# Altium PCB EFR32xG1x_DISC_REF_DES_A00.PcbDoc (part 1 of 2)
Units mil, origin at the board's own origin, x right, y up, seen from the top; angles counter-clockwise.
Board outline 1181.1 x 1771.65 mil, 4 copper layers (Top Layer, Signal Layer 2, Signal Layer 3, Bottom Layer), stack 63.229 mil thick; 88 components, 86 nets, 332 pads, 389 vias.
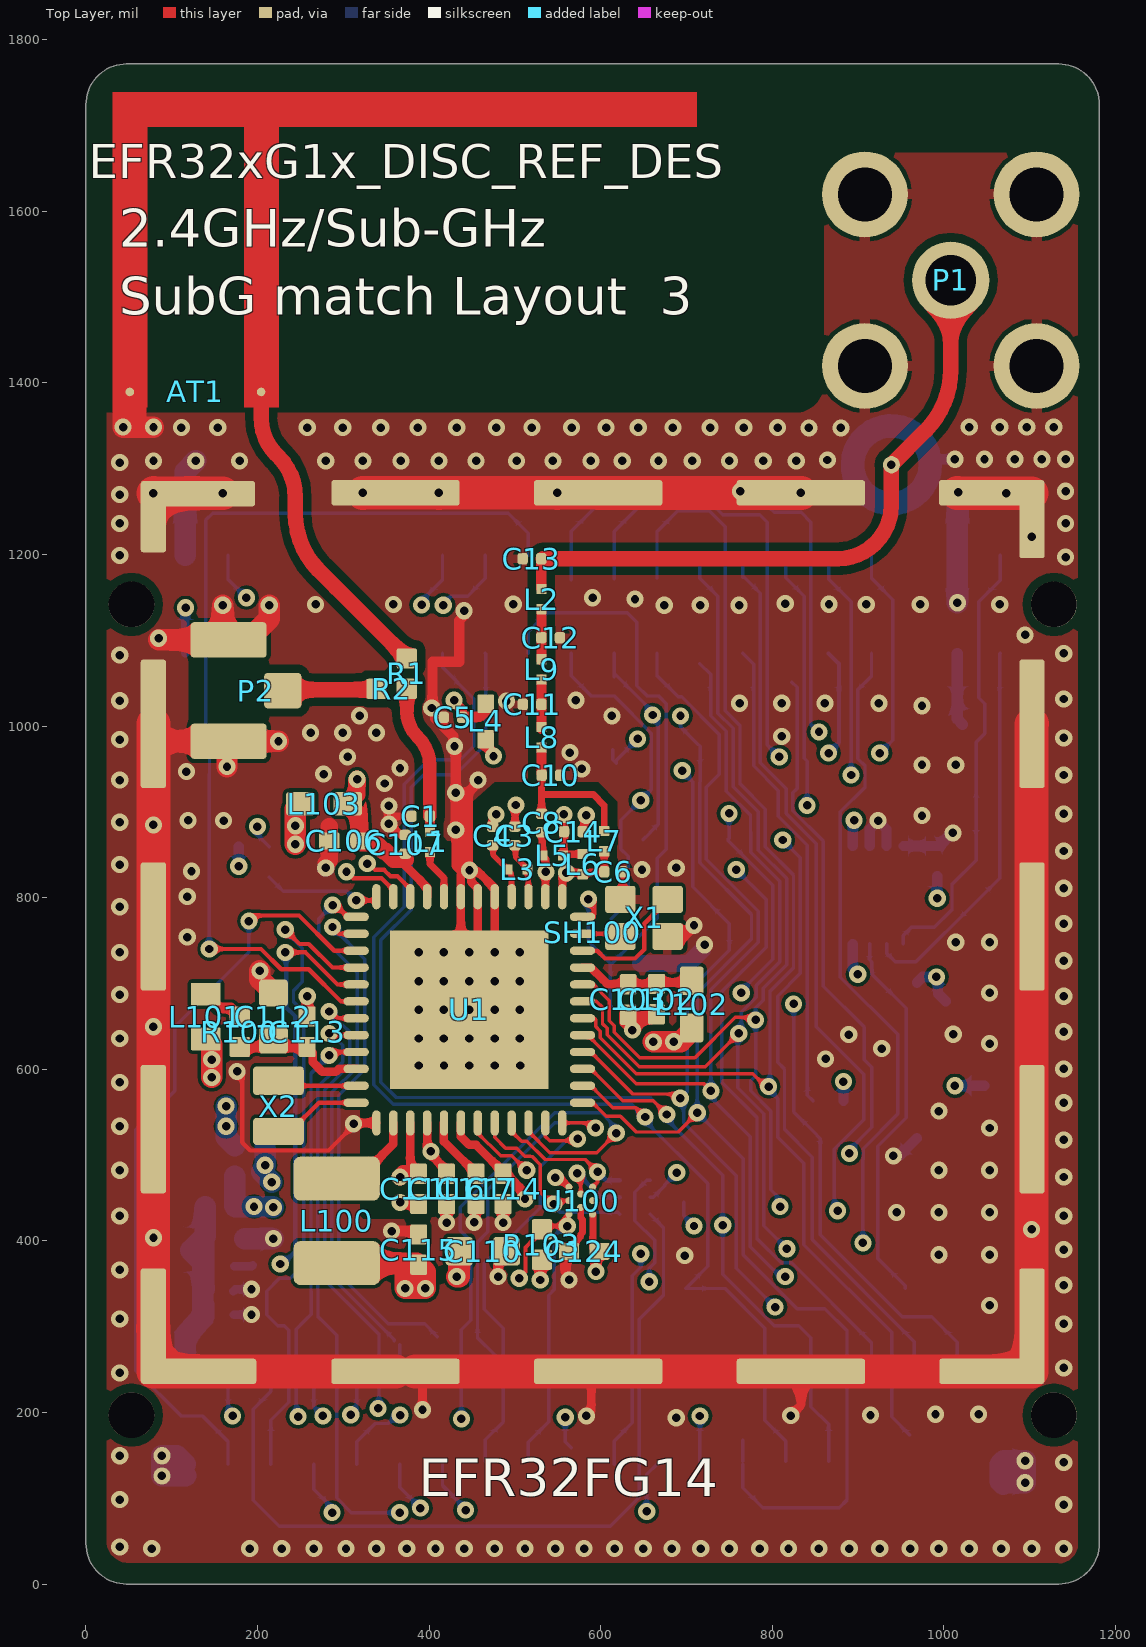
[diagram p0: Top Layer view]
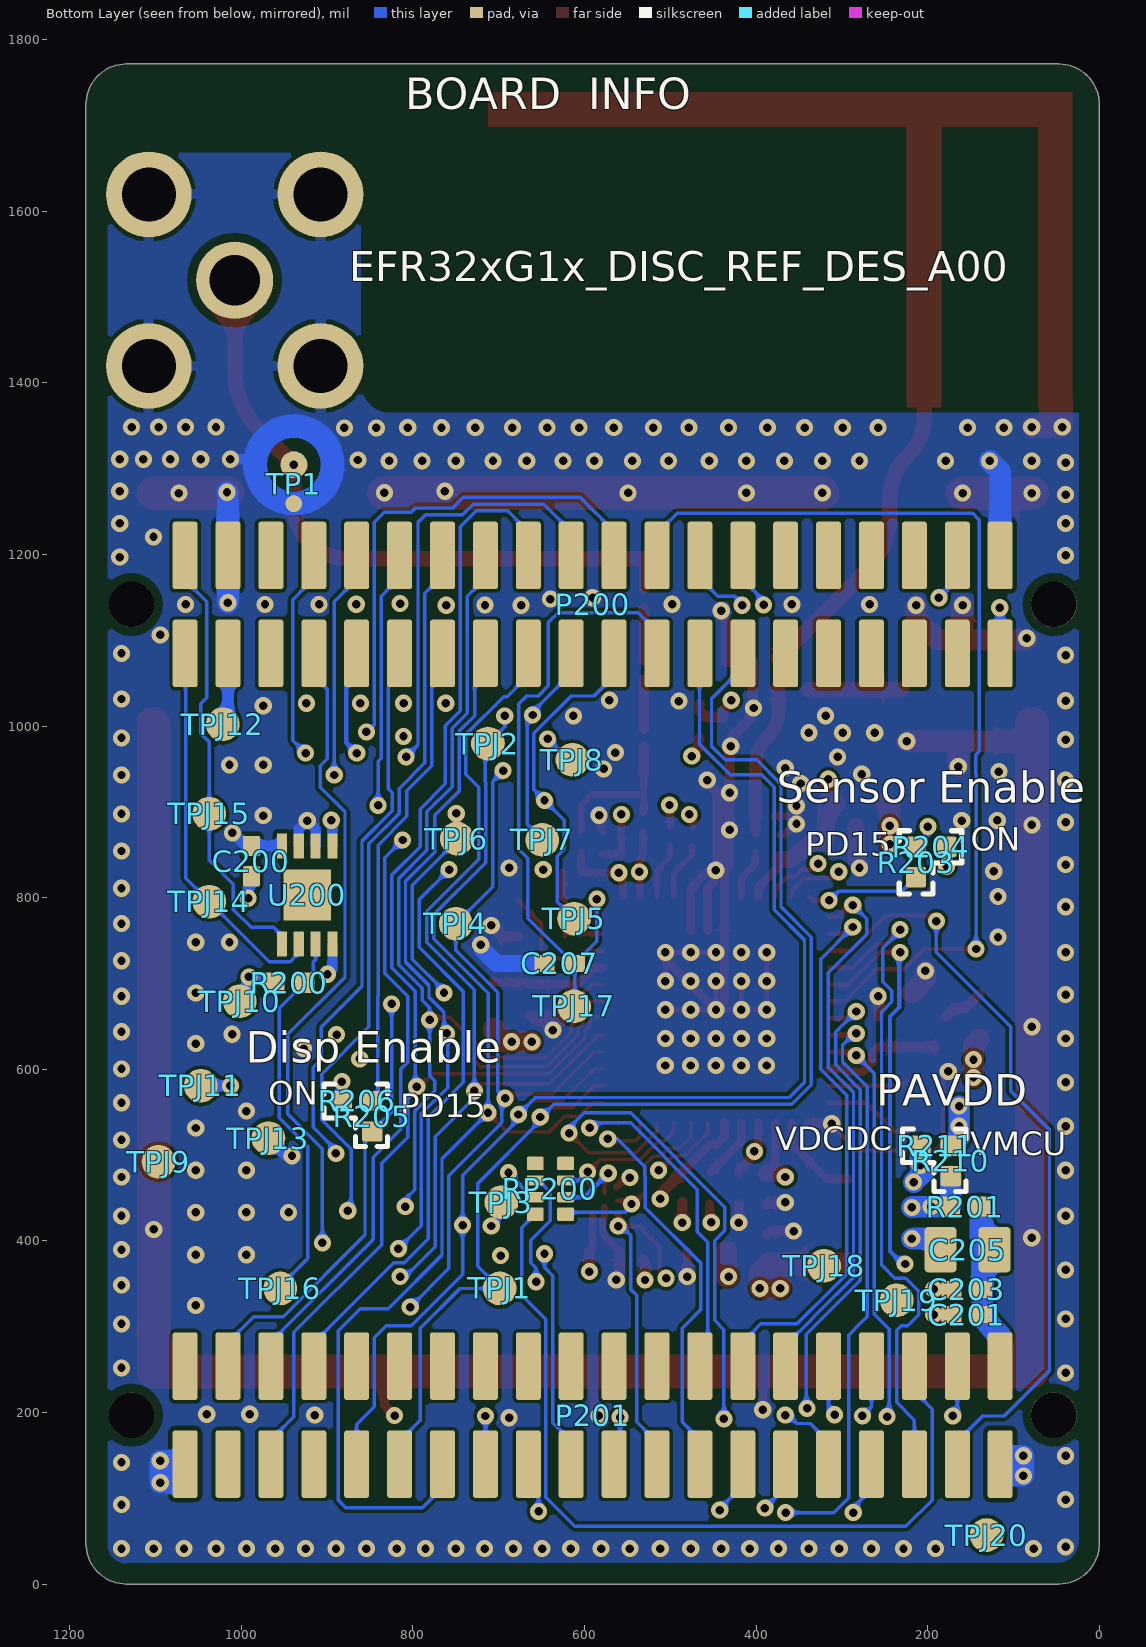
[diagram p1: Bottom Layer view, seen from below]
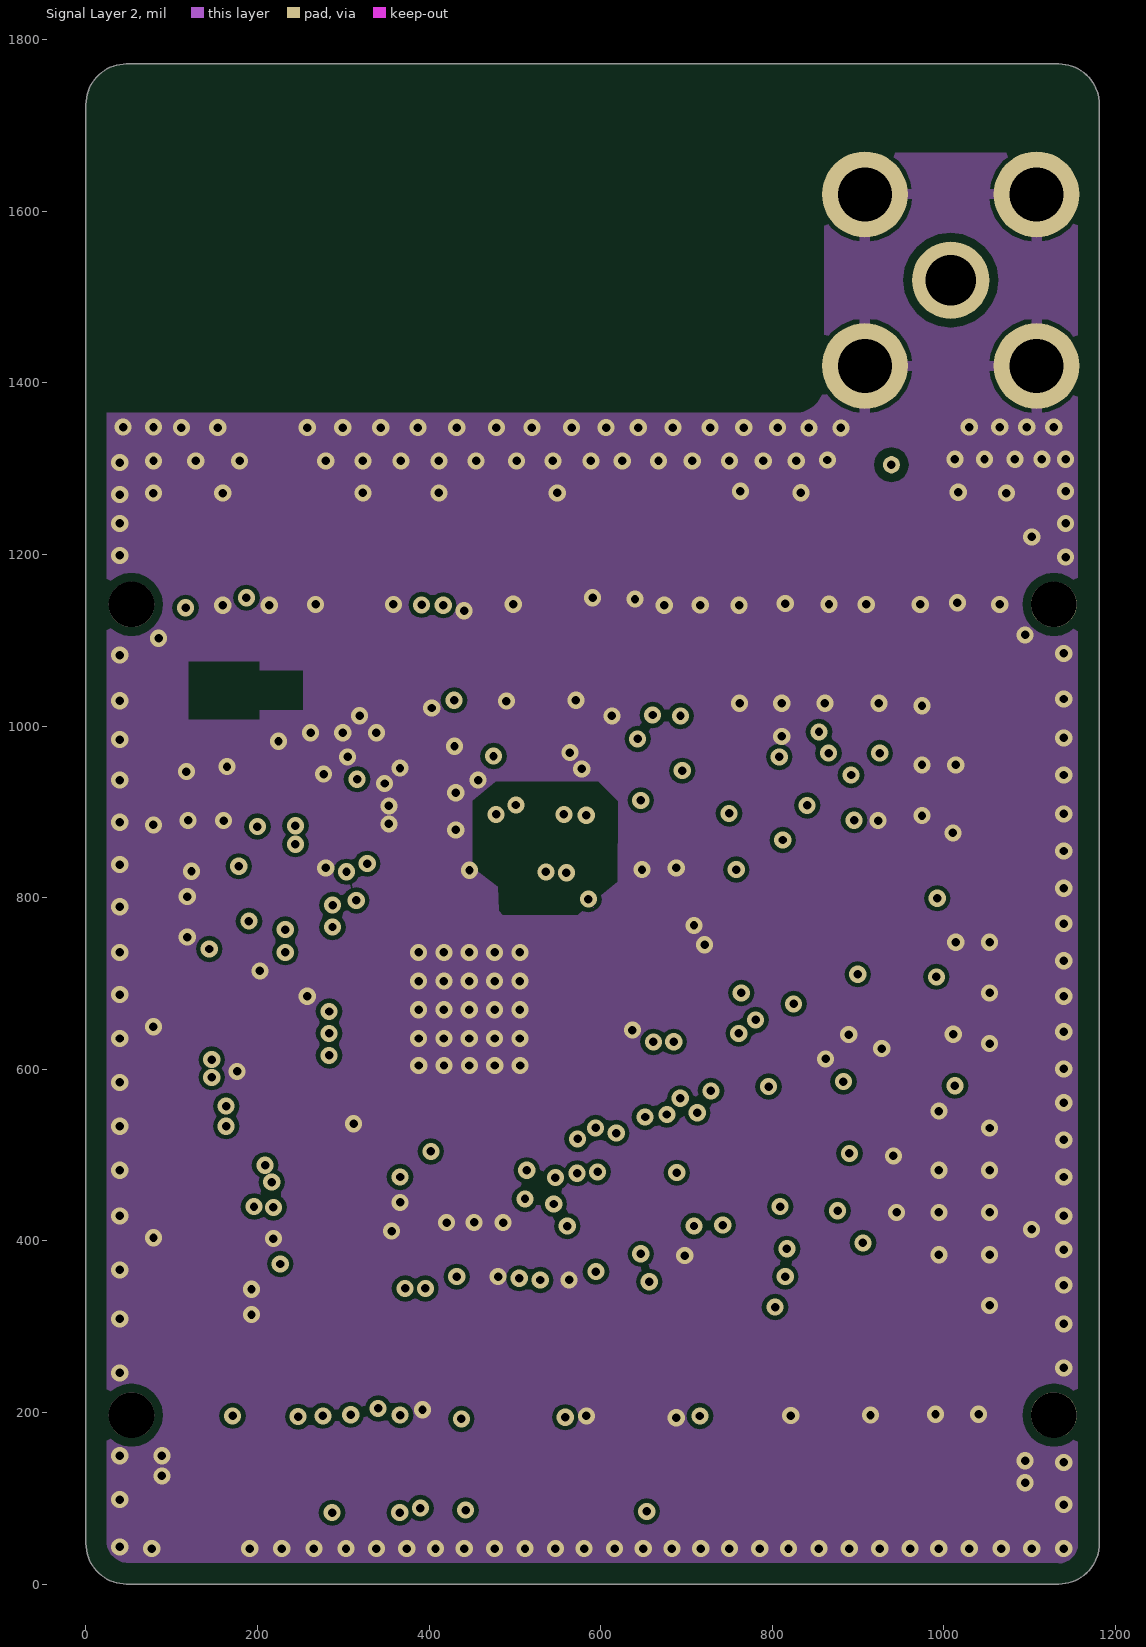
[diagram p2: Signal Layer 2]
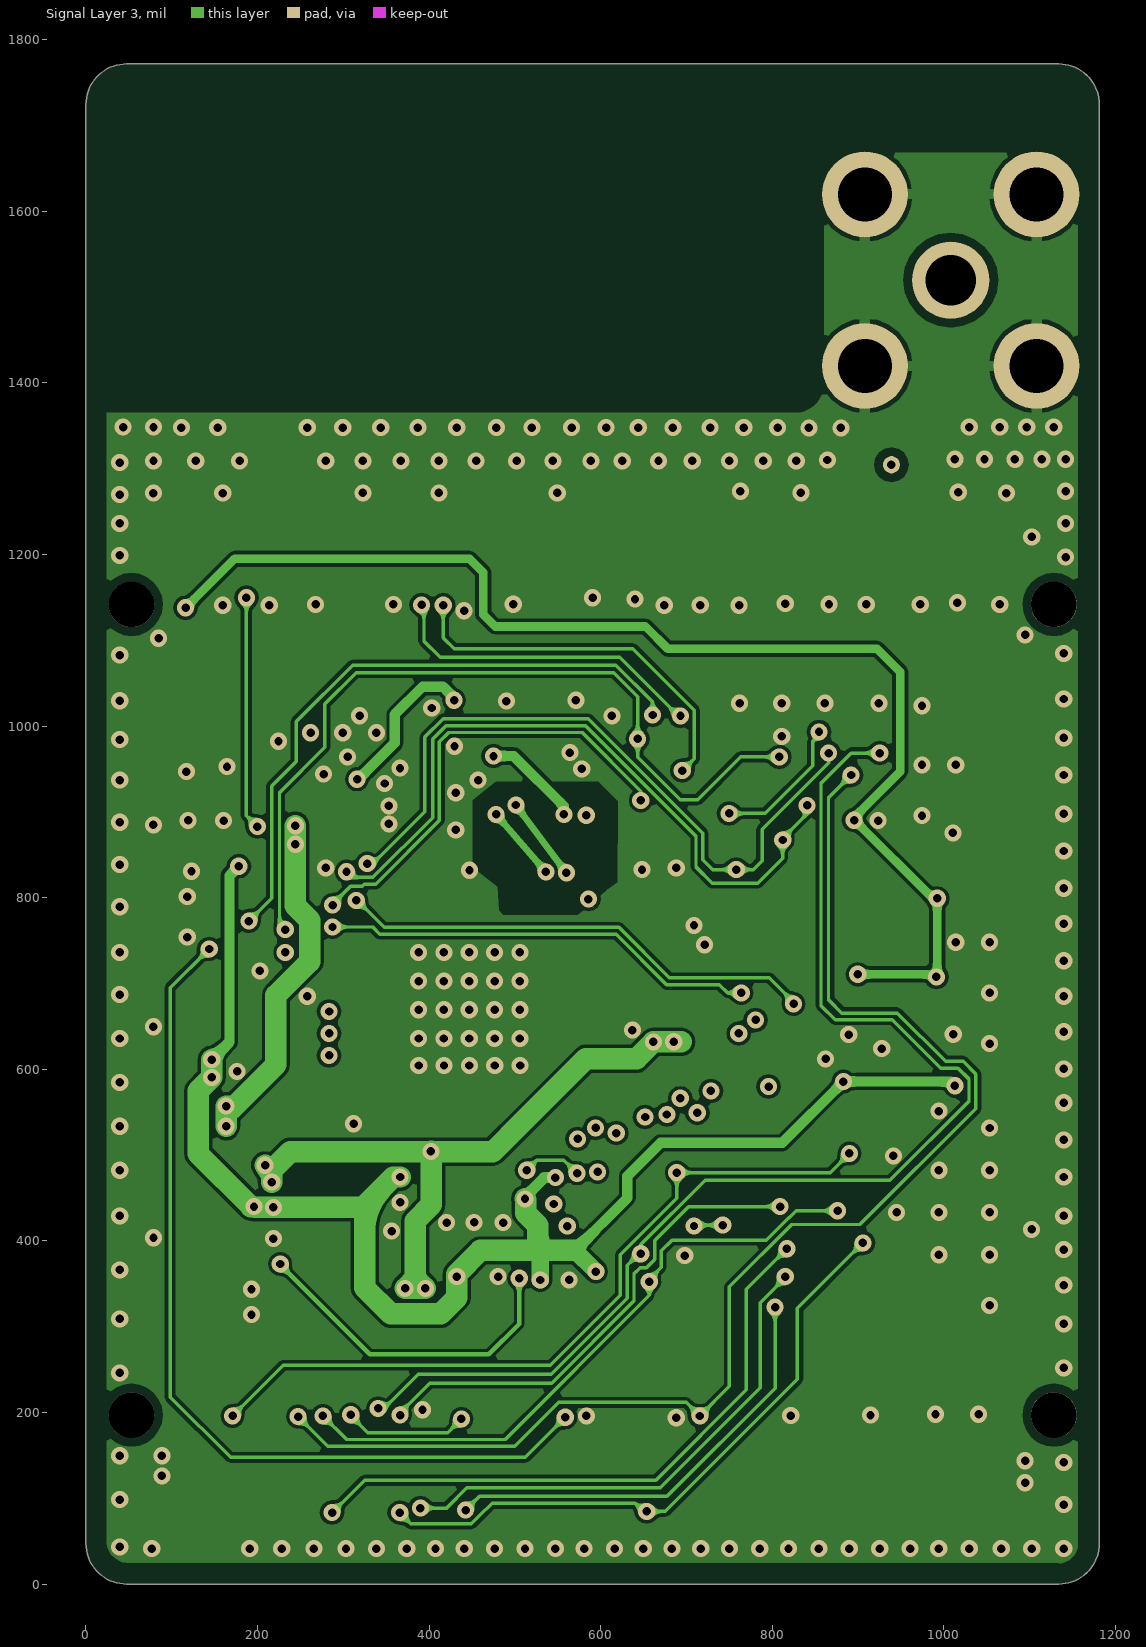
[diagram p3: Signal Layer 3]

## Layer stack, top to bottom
Top Solder: solder mask 0.3937, Solder Resist, Dk 3.5
Top Layer: signal copper 1.378
Dielectric 1: core 11.811, FR-4, Dk 4.2
Signal Layer 2: signal copper 0.7087
Dielectric 3: prepreg 35.4331, Dk 4.2
Signal Layer 3: signal copper 0.7087
Dielectric 2: core 11.811, FR-4, Dk 4.2
Bottom Layer: signal copper 1.378
Bottom Solder: solder mask 0.3937, Solder Resist, Dk 3.5

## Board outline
0,47.24 ccw(c47.24,47.24) 47.24,0 1133.86,0 ccw(c1133.86,47.24) 1181.1,47.24 1181.1,1724.41 ccw(c1133.86,1724.41) 1133.86,1771.65 47.24,1771.65 ccw(c47.24,1724.41) 0,1724.41
cut-out: 592,788
cut-out: 592,789

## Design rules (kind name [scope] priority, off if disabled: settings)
Clearance ClearanceANT1 [InComponent('AT1') vs InNet('50R_IFA')] p1: gap=0 ignorepadtopadclearanceinfootprint=FALSE
Clearance Clearance_to_RF3 [InNet('NetC8_1') vs InNet('GND')] p2: gap=4 ignorepadtopadclearanceinfootprint=FALSE except(0: Arc-Hole Track-Hole SMDPad-Hole THPad-Hole Via-Hole Fill-Hole Poly-Hole Region-Hole Text-Hole; 10: Arc-Fill Arc-Poly Arc-Region Track-Fill Track-Poly Track-Region SMDPad-Fill SMDPad-Poly SMDPad-Region THPad-Fill THPad-Poly THPad-Region Via-Fill Via-Poly Via-Region Fill-Fill Fill-Poly Fill-Region Poly-Poly Poly-Region Region-Region)
Clearance Clearance_to_RF2 [InNet('NetC11_1') vs InNet('GND')] p3: gap=4 ignorepadtopadclearanceinfootprint=FALSE except(0: Arc-Hole Track-Hole SMDPad-Hole THPad-Hole Via-Hole Fill-Hole Poly-Hole Region-Hole Text-Hole; 10: Arc-Fill Arc-Poly Arc-Region Track-Fill Track-Poly Track-Region SMDPad-Fill SMDPad-Poly SMDPad-Region THPad-Fill THPad-Poly THPad-Region Via-Fill Via-Poly Via-Region Fill-Fill Fill-Poly Fill-Region Poly-Poly Poly-Region Region-Region)
Clearance Clearance_to_RF1 [InNet('NetC12_1') vs InNet('GND')] p4: gap=10 ignorepadtopadclearanceinfootprint=FALSE except(0: Arc-Text Arc-Hole Track-Text Track-Hole SMDPad-Text SMDPad-Hole THPad-Text THPad-Hole Via-Text Via-Hole Fill-Text Fill-Hole Poly-Text Poly-Hole Region-Text Region-Hole Text-Text Text-Hole; 4: Arc-Arc Arc-Track Arc-SMDPad Arc-THPad Arc-Via Track-Track Track-SMDPad Track-THPad Track-Via SMDPad-SMDPad SMDPad-THPad SMDPad-Via THPad-THPad THPad-Via Via-Via)
Clearance Clearance_to_Holes [InPadClass('NPTH')] p5: gap=10 ignorepadtopadclearanceinfootprint=FALSE except(0: Arc-Hole Track-Hole SMDPad-Hole THPad-Hole Via-Hole Fill-Hole Poly-Hole Region-Hole Text-Hole)
Clearance Clearance_50Ohm [InNetClass('50Ohm') or InNet('50R_*')] p6: gap=9.84 ignorepadtopadclearanceinfootprint=FALSE except(0: Arc-Hole Track-Hole SMDPad-Hole THPad-Hole Via-Hole Fill-Hole Poly-Hole Region-Hole Text-Hole; 6: Arc-SMDPad Track-SMDPad SMDPad-SMDPad)
Clearance Clerance_Polygon_GND3 [InNamedPolygon('GND_3')] p7: gap=5 ignorepadtopadclearanceinfootprint=FALSE except(0: Arc-Hole Track-Hole SMDPad-Hole THPad-Hole Via-Hole Fill-Hole Poly-Hole Region-Hole Text-Hole)
Clearance Clerance_Polygon_GND2 [InNamedPolygon('GND_2')] p8: gap=5 ignorepadtopadclearanceinfootprint=FALSE except(0: Arc-Hole Track-Hole SMDPad-Hole THPad-Hole Via-Hole Fill-Hole Poly-Hole Region-Hole Text-Hole)
Clearance Clerance_Polygon_GND1 [InNamedPolygon('GND_L2')] p9: gap=5 ignorepadtopadclearanceinfootprint=FALSE except(0: Arc-Hole Track-Hole SMDPad-Hole THPad-Hole Via-Hole Fill-Hole Poly-Hole Region-Hole Text-Hole)
Clearance Clerance_Polygon_GND4 [InNamedPolygon('GND_4')] p10: gap=5 ignorepadtopadclearanceinfootprint=FALSE except(0: Arc-Hole Track-Hole SMDPad-Hole THPad-Hole Via-Hole Fill-Hole Poly-Hole Region-Hole Text-Hole)
Clearance Clearance_General [All] p11: gap=4 ignorepadtopadclearanceinfootprint=FALSE except(0: Arc-Hole Track-Hole SMDPad-Hole THPad-Hole Via-Hole Fill-Hole Poly-Hole Region-Hole Text-Hole)
ComponentClearance ComponentClearanceR1/R2 [InComponent('R1') vs InComponent('R2')] p1: gap=0 collisioncheckmode=3 verticalgap=0 showdistances=FALSE
ComponentClearance ComponentClearanceR203/R204 [InComponent('R203') vs InComponent('R204')] p2: gap=0 collisioncheckmode=3 verticalgap=0 showdistances=FALSE
ComponentClearance ComponentClearanceR205/R206 [InComponent('R205') vs InComponent('R206')] p3: gap=0 collisioncheckmode=3 verticalgap=0 showdistances=FALSE
ComponentClearance ComponentClearanceR210/R211 [InComponent('R210') vs InComponent('R211')] p4: gap=0 collisioncheckmode=3 verticalgap=0 showdistances=FALSE
ComponentClearance [All] p5: gap=7.87 collisioncheckmode=3 verticalgap=10 showdistances=FALSE
HoleToHoleClearance HoleToHoleClearance_ANT1toPAD [Incomponent ('ANT1') vs ISpad] p1: gap=0 allowstackedmicrovias=TRUE
HoleToHoleClearance HoleToHoleClearance_U1toVIA_1 [InComponent ('U1') vs IsVia] p2: gap=0 allowstackedmicrovias=TRUE
HoleToHoleClearance [All] p3: gap=10 allowstackedmicrovias=TRUE
MinimumSolderMaskSliver [All] p1: minsoldermaskwidth=4
PolygonConnect PolygonConnect_SH100 [InComponent('SH100')] p1: connectstyle=Direct reliefconductorwidth=10 reliefentries=4 polygonreliefangle="90 Angle" airgapwidth=5
PolygonConnect PolygonConnect_P1 [InComponent('P1')] p2: connectstyle=Relief reliefconductorwidth=12 reliefentries=4 polygonreliefangle="90 Angle" airgapwidth=5
PolygonConnect Polygon_VIA_Connect [IsVia] p3: connectstyle=Direct reliefconductorwidth=10 reliefentries=4 polygonreliefangle="90 Angle" airgapwidth=10
PolygonConnect PolygonConnect_General [All] p4: connectstyle=NoConnect reliefconductorwidth=10 reliefentries=4 polygonreliefangle="90 Angle" airgapwidth=5
RoutingVias [All] p1: holewidth=9.84 width=20 viastyle="Through Hole" minholewidth=9.84 minwidth=20 maxholewidth=39.37 maxwidth=59.06
ShortCircuit ShortCircuitANT1 [InComponent('AT1') vs (InNet('50R_IFA') Or InNet('GND'))] p1: allowed=TRUE
SilkToSilkClearance [All] p1: silktosilkclearance=4
SilkToSolderMaskClearance [IsPad] p1: minsilkscreentomaskgap=4 clearancetoexposedcopper=TRUE
SolderMaskExpansion [All] p1: expansion=2
Width [All] p1: maxlimit=200 minlimit=4 preferedwidth=8
24 further rules are at their usual default settings.

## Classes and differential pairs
net class WSTK_P[45..0]: WSTK_P3 WSTK_P15 WSTK_P17 WSTK_P19 WSTK_P21 WSTK_P23 WSTK_P25 WSTK_P27 WSTK_P29 WSTK_P30 WSTK_P34 WSTK_P36 WSTK_P37 WSTK_P38 WSTK_P39 WSTK_P40 WSTK_P41 WSTK_P42 WSTK_P43 WSTK_P44 WSTK_P45
net class WSTK_F[21..0]: WSTK_F4 WSTK_F14 WSTK_F15 WSTK_F16
net class RADIO_PF[7..0]: RADIO_PF0 RADIO_PF1 RADIO_PF2 RADIO_PF3 RADIO_PF4 RADIO_PF5 RADIO_PF6 RADIO_PF7
net class RADIO_PD[15..13]: RADIO_PD13 RADIO_PD14 RADIO_PD15
net class RADIO_PC[11..6]: RADIO_PC6 RADIO_PC7 RADIO_PC8 RADIO_PC9 RADIO_PC10 RADIO_PC11
net class RADIO_PB[15..11]: RADIO_PB11 RADIO_PB12 RADIO_PB13 RADIO_PB14 RADIO_PB15
net class RADIO_PA[5..0]: RADIO_PA0 RADIO_PA1 RADIO_PA2 RADIO_PA3 RADIO_PA4 RADIO_PA5
component class "04_ WSTK Connectors & B": C200 C201 C203 C205 P200 P201 R200 R201 TPJ1 TPJ2 TPJ3 TPJ4 TPJ5 TPJ6 TPJ7 TPJ8 TPJ9 TPJ10 TPJ11 TPJ12 TPJ13 TPJ14 TPJ15 TPJ16 TPJ17 TPJ18 TPJ19 TPJ20 U200
component class "03_ EFR32 Signal Assign": C124 C207 R103 R203 R204 R205 R206 RP200 U1 U100
component class "02_ RF, Antenna & Power": AT1 C1 C3 C4 C5 C6 C8 C10 C11 C12 C13 C14 C102 C103 C106 C107 C110 C111 C112 C113 C114 C115 C116 C117 L1 L2 L3 L4 L5 L6 L7 L8 L9 L100 L101 L102 L103 P1 P2 R1 R2 R100 R210 R211 SH100 SH101 TP1 X1 X2
pad class NPTH: P200-M1 P200-M2 P201-M1 P201-M2

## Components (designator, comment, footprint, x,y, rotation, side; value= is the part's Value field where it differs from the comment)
AT1 "INVERTED_F" ANT_INV_F_2.4_GHZ_17.3MM_MIR 31.1,1371.65 r0 top locked
C1 "1P5" C0201_L 390,895 r0 top
C3 "1P8" C0201_L 500,872 r270 top
C4 "1P8" C0201_L 474,872 r270 top
C5 "270pF" C0201_L 427.83,1010 r180 top
C6 "5.1P" C0201_L 614.83,830 r0 top
C8 "4P7" C0201_L 531,887 r270 top
C10 "6P2" C0201_L 542,942.66 r0 top
C11 "5.6P" C0201_L 520,1025.23 r180 top
C12 "5P6" C0201_L 541.61,1103 r0 top
C13 "NC" C0201_L 519.83,1195 r180 top
C14 "2P" C0201_L 568,877 r0 top
C102 "100PF" C0402_L 665,681.72 r270 top
C103 "10PF" C0402_L 632,681.28 r270 top
C106 "220NF" C0402_L 301.18,866.14 r180 top
C107 "10P" C0201_L 372.05,862.2 r90 top
C110 "10UF" C0603_L 462.6,387.8 r0 top
C111 "1UF" C0402_L 387.72,460.63 r270 top
C112 "10UF" C0603_L 218.5,661.42 r90 top
C113 "10NF" C0402_L 257.8,643.7 r90 top
C114 "1UF" C0402_L 486.22,460.63 r270 top
C115 "4.7uF" C0402_L 387.8,389.76 r90 top
C116 "100NF" C0402_L 420.28,460.63 r270 top
C117 "1UF" C0402_L 454.72,460.63 r270 top
C124 "100NF" C0402_L 580.71,387.8 r180 top
C200 "100N" C0402_L 988.19,842.52 r90 bottom
C201 "100N" C0402_L 154.53,313.98 r0 bottom
C203 "100N" C0402_L 154.53,343.5 r0 bottom
C205 "10U" C0805_L 153.54,389.76 r0 bottom
C207 "100N" C0402_L 628.94,723.43 r0 bottom
Designator16 "Comment" PCB_SPEC_4_LAYER 1393.94,20246.04 r0 top
L1 "1N9" COIL_0201_L 401,865 r90 top
L2 "120P" COIL_0201_L 531,1148 r270 top
L3 "75NH" COIL_0201_L 503,833 r180 top
L4 "330NH" COIL_0402_L 466,1005.33 r270 top
L5 "12NH" COIL_0201_L 544,849 r180 top
L6 "12NH" COIL_0201_L 579,839 r90 top
L7 "27NH" COIL_0201_L 604,865.81 r270 top
L8 "24NH" COIL_0201_L 531,987 r270 top
L9 "24NH" COIL_0201_L 531,1066 r270 top
L100 "4.7UH" COIL_MUR_LQH3NP_1212 292.32,423.23 r270 top
L101 "CBF102WB" WURTH_CBF_0603 139.76,661.42 r90 top
L102 "BLM18AG601SN1" COIL_MUR_BLM18_0603 706,675.56 r90 top
L103 "BLM18AG601SN1" COIL_MUR_BLM18_0603 277.56,909.45 r0 top
P1 "SMA" TE_SMA_TH_1814832 1007.87,1519.68 r0 top locked
P2 "U.FL" HIROSE_U.FL-R-SMT-1 166.34,1041.34 r270 top
P200 "SOCKET_2X20_1.27MM_SMD" SAM_SFC-120-T2-D-A-2X20_SNUM 590.55,1141.73 r0 bottom locked
P201 "SOCKET_2X20_1.27MM_SMD" SAM_SFC-120-T2-D-A-2X20_SNUM 590.55,196.85 r0 bottom locked
R1 "0R" R0402_L 374.02,1061.02 r90 top
R2 "0R" R0402_L 356.3,1043.31 r180 top
R100 "1R" R0402_L 179.13,643.7 r270 top
R103 "330K" R0402_L 531.5,395.67 r90 top
R200 "10K" R0402_L 944,700.79 r0 bottom
R201 "0R" R0402_L 156.5,439.96 r0 bottom
R203 "0R" R0402_L 213.58,841.54 r90 bottom
R204 "0R" R0402_L 195.87,859.25 r0 bottom
R205 "0R" R0402_L 847.44,545.28 r90 bottom
R206 "0R" R0402_L 865.16,562.99 r180 bottom
R210 "0R" R0402_L 173.23,493.11 r270 bottom
R211 "0R" R0402_L 190.94,510.83 r0 bottom
RP200 "100R" RES_MNR04-8 639.76,460.63 r90 bottom
SH100 "RF_SHIELD_FRAME_BMI-S-203-F" RF_SHIELD_FRAME_BMI-S-203-F_PCB4100 590.55,759.84 r0 top locked
TP1 "RF_TEST_POINT" "TP_INGUN_50_OHM_CLOSED openvia" 938.78,1304.53 r180 bottom locked
TPJ1 "TPJ_SMD" TP_1.0_SMD#1 698.82,344.49 r90 bottom locked
TPJ2 "TPJ_SMD" TP_1.0_SMD#1 712.6,979.53 r90 bottom locked
TPJ3 "TPJ_SMD" TP_1.0_SMD#1 696.85,444.88 r90 bottom locked
TPJ4 "TPJ_SMD" TP_1.0_SMD#1 750,769.68 r90 bottom locked
TPJ5 "TPJ_SMD" TP_1.0_SMD#1 612.2,775.59 r90 bottom locked
TPJ6 "TPJ_SMD" TP_1.0_SMD#1 748.82,868.9 r90 bottom locked
TPJ7 "TPJ_SMD" TP_1.0_SMD#2 649.21,867.32 r90 bottom locked
TPJ8 "TPJ_SMD" TP_1.0_SMD#1 614.17,960.63 r90 bottom locked
TPJ9 "TPJ_SMD" TP_1.0_SMD#1 1096.46,492.13 r90 bottom locked
TPJ10 "TPJ_SMD" TP_1.0_SMD#1 1001.97,679.13 r90 bottom locked
TPJ11 "TPJ_SMD" TP_1.0_SMD#1 1047.24,580.71 r90 bottom locked
TPJ12 "TPJ_SMD" TP_1.0_SMD#1 1021.65,1001.97 r90 bottom locked
TPJ13 "TPJ_SMD" TP_1.0_SMD#1 968.5,519.68 r90 bottom locked
TPJ14 "TPJ_SMD" TP_1.0_SMD#1 1037.4,795.28 r90 bottom locked
TPJ15 "TPJ_SMD" TP_1.0_SMD#1 1037.4,897.64 r90 bottom locked
TPJ16 "TPJ_SMD" TP_1.0_SMD#1 954.72,344.49 r90 bottom locked
TPJ17 "TPJ_SMD" TP_1.0_SMD#1 612.2,673.23 r90 bottom locked
TPJ18 "TPJ_SMD" TP_1.0_SMD#1 320.87,370.87 r90 bottom locked
TPJ19 "TPJ_SMD" TP_1.0_SMD#1 236.22,330.71 r90 bottom locked
TPJ20 "TPJ_SMD" TP_1.0_SMD#1 131.5,57.09 r90 bottom locked
U1 "EFR32FG14P233F256GM48" QFN48_M050_SQ7.0_EP_SL_L 446.85,669.29 r180 top
U100 "MX25R8035F" BGA8_M040_1.24x1.75_WLCSP 576.69,446.85 r180 top
U200 "24AA024" TDFN8_M050_2.0x3.0_EP 923.23,803.15 r0 bottom
X1 "38.400 MHz" X_SSS_DSX211SH_2.05X1.65-4 650.44,776.35 r0 top
X2 "32.768 kHz" X_MCS_CM8V-T1A 224.33,557.09 r90 top

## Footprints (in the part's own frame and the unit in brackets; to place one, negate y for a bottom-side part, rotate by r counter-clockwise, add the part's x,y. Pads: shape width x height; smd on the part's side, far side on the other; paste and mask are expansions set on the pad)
ANT_INV_F_2.4_GHZ_17.3MM_MIR [mil] "Antenna inverted F, 2.4 GHz, 17.3 mm (MIR)"
  round 10 smd paste-5 mask-5: 1(173,17.72) 2(20.01,17.72)
  Top Layer region: 0.36,367.2 681,367.2 681,327.07 193.36,327.07 193.36,0 153.36,0 153.36,327.07 40.36,327.07 40.36,0 20.36,0 0.36,0
BGA8_M040_1.24x1.75_WLCSP [mm] "BGA, 8 pin. U100"
  round 0.21 smd mask+0.051: A1(-0.35,0.4) A3(0.35,0.4) B2(0,0.2) C1(-0.35,0) C3(0.35,0) D2(0,-0.2) E1(-0.35,-0.4) E3(0.35,-0.4)
  body extent -0.63,-0.89 0.63,0.88, height 0.52
C0201_L [mm]
  rrect52% 0.31x0.34 smd: 1(-0.275,0) 2(0.275,0)
  body extent -0.3,-0.15 0.3,0.15, height 0.3
C0402_L [mm] "Chip Capacitor, 2-Leads, Body 1.0x0.5mm, IPC High Density"
  rrect20% 0.6x0.5 smd mask+0.051: 1(-0.45,0) 2(0.45,0)
  body extent -0.5,-0.25 0.5,0.25, height 0.6
C0603_L [mm] "Capacitor, 0603, High Density (C)"
  rrect25% 0.8x0.85 smd: 1(-0.7,0) 2(0.7,0)
  body extent -0.88,-0.48 0.87,0.48, height 0.95
C0805_L [mm] "Capacitor, 0805"
  rrect25% 0.95x1.35 smd: 1(-0.8,0) 2(0.8,0)
  body extent -1.1,-0.72 1.1,0.72, height 1.45
COIL_0201_L [mm]
  rrect10% 0.3x0.3 smd: 1(-0.3,0) 2(0.3,0)
  body extent -0.32,-0.17 0.32,0.17, height 0.33
COIL_0402_L [mm]
  rrect20% 0.55x0.5 smd mask+0.051: 1(-0.525,0) 2(0.525,0)
  body extent -0.5,-0.25 0.5,0.25, height 0.6
COIL_MUR_BLM18_0603 [mm] "COIL_MUR_BLM18P_0603"
  rrect25% 0.85x0.7 smd mask+0.051: 1(-0.7,0) 2(0.7,0)
  body extent -0.88,-0.48 0.87,0.48, height 0.95
COIL_MUR_LQH3NP_1212 [mm] "COIL_MUR_LQH3NP_1212"
  rrect30% 1.3x2.55 smd mask+0.051: 1(-1.25,0) 2(1.25,0)
  body extent -1.6,-1.6 1.6,1.6, height 1.5
HIROSE_U.FL-R-SMT-1 [mm] "COAX_HIROSE_U.FL_CL331-0471"
  rrect20% 1.05x1.1 smd mask+0.051: 1(0,1.6)
  rrect20% 1.05x2.25 smd mask+0.051: 2(-1.5,0) 3(1.5,0)
  Top Layer pour cut-out: -0.85,0.9 0.85,0.9 0.85,0.9 0.85,-1.2 -0.85,-1.2 -0.85,-1.2
  body extent -1.3,-1.55 1.3,1.3, height 0.9
PCB_SPEC_4_LAYER [mil]
QFN48_M050_SQ7.0_EP_SL_L [mm] "QFN48_M050_SQ7.0_EP, SiLabs, High Density (C)"
  oval 0.75x0.25 smd: 1(-3.35,2.75) 2(-3.35,2.25) 3(-3.35,1.75) 4(-3.35,1.25) 5(-3.35,0.75) 6(-3.35,0.25) 7(-3.35,-0.25) 8(-3.35,-0.75) 9(-3.35,-1.25) 10(-3.35,-1.75) 11(-3.35,-2.25) 12(-3.35,-2.75) 25(3.35,-2.75) 26(3.35,-2.25) 27(3.35,-1.75) 28(3.35,-1.25) 29(3.35,-0.75) 30(3.35,-0.25) 31(3.35,0.25) 32(3.35,0.75) 33(3.35,1.25) 34(3.35,1.75) 35(3.35,2.25) 36(3.35,2.75)
  oval 0.25x0.75 smd: 13(-2.75,-3.35) 14(-2.25,-3.35) 15(-1.75,-3.35) 16(-1.25,-3.35) 17(-0.75,-3.35) 18(-0.25,-3.35) 19(0.25,-3.35) 20(0.75,-3.35) 21(1.25,-3.35) 22(1.75,-3.35) 23(2.25,-3.35) 24(2.75,-3.35) 37(2.75,3.35) 38(2.25,3.35) 39(1.75,3.35) 40(1.25,3.35) 41(0.75,3.35) 42(0.25,3.35) 43(-0.25,3.35) 44(-0.75,3.35) 45(-1.25,3.35) 46(-1.75,3.35) 47(-2.25,3.35) 48(-2.75,3.35)
  rrect50% 1.9x1.9 on Top Paste mask-0.805: 49(-1.15,1.15) 49(-1.15,-1.15) 49(1.15,1.15) 49(1.15,-1.15)
  rect 4.7x4.7 smd paste-4.7: 49(0,0)
  body extent -3.5,-3.5 3.5,3.5, height 0.9
R0402_L [mm] "Chip Resistor, 2-Leads, Body 1.0x0.5mm, IPC High Density"
  rrect20% 0.6x0.6 smd mask+0.051: 1(-0.45,0) 2(0.45,0)
  body extent -0.5,-0.25 0.5,0.25, height 0.6
RES_MNR04-8 [mm] "Chip resistor network 8pin"
  rrect20% 0.4x0.5 smd mask+0.051: 1(-0.75,-0.45) 4(0.75,-0.45) 5(0.75,0.45) 8(-0.75,0.45)
  rrect20% 0.3x0.5 smd mask+0.051: 2(-0.25,-0.45) 3(0.25,-0.45) 6(0.25,0.45) 7(-0.25,0.45)
  body extent -1,-0.4 1,0.4, height 0.5
RF_SHIELD_FRAME_BMI-S-203-F_PCB4100 [mm] "RF_SHIELD_FRAME_BMI-S-203-F"
  rrect20% 0.75x3.8 smd paste+0 mask+0.05: 1(-13.005,-5.835) 1(-13.005,0.165) 1(-13.005,6.165) 1(13.005,-5.835) 1(13.005,0.165) 1(13.005,6.165)
  rrect20% 0.75x3.4 smd paste+0 mask+0.05: 1(-13.005,-11.659) 1(13.005,-11.659)
  rrect20% 0.75x2.1 smd paste+0 mask+0.05: 1(-13.005,12.294)
  oval 0.75x0.254 smd paste+0 mask+0.05: 1(-13.004,12.994) 1(12.994,12.994) 1(12.994,12.994) 1(12.994,12.994)
  rrect20% 3.375x0.75 smd paste+0 mask+0.05: 1(-11.684,12.979)
  rrect20% 3.4x0.75 smd paste+0 mask+0.05: 1(-11.659,-13.005)
  rrect20% 3.8x0.75 smd paste+0 mask+0.05: 1(-5.835,-13.005) 1(-5.835,13.005) 1(0.165,-13.005) 1(0.165,13.005) 1(6.165,-13.005) 1(6.165,13.005)
  rrect20% 3.1x0.75 smd paste+0 mask+0.05: 1(11.811,-13.005)
  rrect20% 3.125x0.75 smd paste+0 mask+0.05: 1(11.811,13.005)
  rrect20% 0.75x2.3 smd paste+0 mask+0.05: 1(13.005,12.217)
  body extent -13.3,-13.3 13.3,13.3, height 5.5
SAM_SFC-120-T2-D-A-2X20_SNUM [mm]
  rrect20% 0.74x2 smd mask+0.05: 1(-12.065,1.45) 2(-12.065,-1.45) 3(-10.795,1.45) 4(-10.795,-1.45) 5(-9.525,1.45) 6(-9.525,-1.45) 7(-8.255,1.45) 8(-8.255,-1.45) 9(-6.985,1.45) 10(-6.985,-1.45) 11(-5.715,1.45) 12(-5.715,-1.45) 13(-4.445,1.45) 14(-4.445,-1.45) 15(-3.175,1.45) 16(-3.175,-1.45) 17(-1.905,1.45) 18(-1.905,-1.45) 19(-0.635,1.45) 20(-0.635,-1.45) 21(0.635,1.45) 22(0.635,-1.45) 23(1.905,1.45) 24(1.905,-1.45) 25(3.175,1.45) 26(3.175,-1.45) 27(4.445,1.45) 28(4.445,-1.45) 29(5.715,1.45) 30(5.715,-1.45) 31(6.985,1.45) 32(6.985,-1.45) 33(8.255,1.45) 34(8.255,-1.45) 35(9.525,1.45) 36(9.525,-1.45) 37(10.795,1.45) 38(10.795,-1.45) 39(12.065,1.45) 40(12.065,-1.45)
  round 1.35 hole 1.35 unplated paste-5.563 mask-5.563: M1(13.652,0) M2(-13.652,0)
  body extent -14.65,-1.58 14.65,2.25, height 4.57
TDFN8_M050_2.0x3.0_EP [mm] "TDFN8_M050_2.0x3.0_EP"
  rrect20% 0.3x0.75 smd mask+0.051: 1(-0.75,-1.45) 2(-0.25,-1.45) 3(0.25,-1.45) 4(0.75,-1.45) 5(0.75,1.45) 6(0.25,1.45) 7(-0.25,1.45) 8(-0.75,1.45)
  rect 1.4x1.5 smd mask+0.051: 9(0,0)
  body extent -1,-1.5 1,1.5, height 1
TE_SMA_TH_1814832 [mm]
  round 2.286 hole 1.5: 1(0,0)
  round 2.54 hole 1.6: 2(-2.54,-2.54) 3(2.54,-2.54) 4(2.54,2.54) 5(-2.54,2.54)
  body extent -3.2,-3.2 3.2,3.2, height 9.5
TP_1.0_SMD#1 [mm] "Test Point, 1.0 mm, SMD"
  round 1 smd paste-0.501: 1(0,0)
TP_1.0_SMD#2 [mm] "Test Point, 1.0 mm, SMD"
  round 1 smd: 1(0,0)
"TP_INGUN_50_OHM_CLOSED openvia" [mm] "TP_INGUN_50_OHM_CLOSED"
  round 0.8 / inner round 0.508 / far side round 0.508 hole 0.25 mask+0: 1(0,0)
  round 0.5 smd paste-0.255 mask-0.41: 2(0,-1.15)
  Top Layer lines w0.7: 0,-1.15 cw(c0,0) -1.15,0 cw(c0,0) 0,-1.15
WURTH_CBF_0603 [mm] "COIL_WURTH_CBF_0603_L (= L0603_0.8_L)"
  rrect10% 0.67x0.88 smd: 1(-0.665,0) 2(0.665,0)
  body extent -0.87,-0.48 0.87,0.48, height 0.95
X_MCS_CM8V-T1A [mm] "Crystal MCS CM8V-T1A (2 pin)"
  rrect25% 0.8x1.5 smd paste-0.15 mask+0.051: 1(-0.75,0)
  rrect25% 0.85x1.5 smd paste-0.15 mask+0.051: 2(0.75,0)
  body extent -1,-0.6 1,0.6, height 0.97
X_SSS_DSX211SH_2.05X1.65-4 [mm] "X_SSS_DSX211SH_2.05X1.65-4"
  rrect20% 0.9x0.8 smd mask+0.051: 1(-0.7,-0.55) 2(0.7,-0.55) 3(0.7,0.55) 4(-0.7,0.55)
  body extent -1.07,-0.87 1.07,0.87, height 0.5

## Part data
AT1: library part ANT_INVERTED_F
C1 C3 C4: library part C0402, Tolerance=?.05P
C5 C10: library part C0402, Tolerance=?.1P
C6: library part C0402
C8 C11 C14: library part C0402, Tolerance=?%
C12 C13: library part C0402, Tolerance=?.05pF
C102 C103 C107: library part C0402, Rating=50V, Tolerance=5%
C106 C113 C116 C124 C200 C201 C203 C207: library part C0402, Rating=16V, Tolerance=10%
C110 C112: library part C0603, Rating=6.3V, Tolerance=20%
C111 C114 C117: library part C0402, Rating=25V, Tolerance=10%
C115: library part C0402, Rating=6.3V, Tolerance=10%
C205: library part C0805, Rating=10V, Tolerance=10%
L1: library part L0402, Tolerance=?.05N
L2 L7 L8 L9: library part L0402, Tolerance=?%
L3 L5 L6: library part L0402
L4: library part L0603
L100: library part LQH3NP
L102 L103: library part BLM18AG
P1: library part SMA_TH
P2: library part HIROSE_U.FL
R1 R2 R100 R103 R200 R201 R203 R204 R205 R206 R210 R211: library part R0402
RP200: library part MNR04M0APJ101
TP1: library part TP_RF
U1: library part EFR32-DUALBAND-QFN48
U100: library part MX25R8035
X1: library part DSX211SH
X2: library part CM8V-T1A

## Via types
v1: diameter 20, hole 9.84, Top Layer to Bottom Layer, tented both sides, 385 vias
v2: diameter 19.68, hole 9.84, Top Layer to Bottom Layer, tented both sides, 2 vias
v3: diameter 20, hole 9.84, Top Layer to Bottom Layer, 2 vias

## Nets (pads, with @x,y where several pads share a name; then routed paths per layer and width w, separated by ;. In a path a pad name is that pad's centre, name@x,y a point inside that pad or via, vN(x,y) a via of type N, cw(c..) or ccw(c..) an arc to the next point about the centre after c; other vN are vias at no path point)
3V3: C200.1 P200.1 R200.2 TPJ10.1 U200.1 U200.8 | length 1657.4
  Signal Layer 3 w10: v1(116.14,1137.8) 173.23,1194.88 447.12,1194.88 463,1179 463,1130 477,1116 652,1116 678,1090 922,1090 949,1063 949,947.03 895.2,893.23 v1(895.2,890.28) 895.85,890.28 986.91,799.21 v1(992.13,799.21) v1@992.13,708.66 ; v1(899.61,710.63) 990.16,710.63 v1@990.67,710.12
  Bottom Layer w10: P200.1@115.55,1084.65 115.55,1137.2 v1(116.14,1137.8)
  Bottom Layer w12: U200.8@893.7,746.06 893.7,716.53 v1(899.61,710.63) ; U200.1@893.7,860.24 893.7,888.78 v1(895.2,890.28) ; R200.2@968.5,700.79 975.39,707.68 v1(991.14,707.68) 993.11,705.71 993.11,687.99 TPJ10.1@1001.97,679.13 ; v1(992.13,799.21) C200.1@992.13,824.8
5V: P200.37 TPJ12.1 | length 85.2
  Bottom Layer w13: P200.37@1015.55,1084.65 1015.55,1008.07 TPJ12.1@1021.65,1001.97
50R_IFA: AT1.1 R1.2 | length 368
  Top Layer w18: AT1.1@204.1,1389.37 204.1,1359.85 ccw(c265.83,1359.85) 222.18,1316.2 ; 224.64,1313.75 cw(c177.56,1266.73) 244.09,1266.73 244.09,1247.64 ccw(c338.19,1247.64) 271.65,1181.1 291.34,1161.42 R1.2@374.02,1078.74
50R_R1: C1.2 L1.2 R1.1 R2.1 | length 172.2
  Top Layer w8: L1.2@400.91,876.9 L1.2@401,876.81
  Top Layer w12: L1.2@400.91,876.9 C1.2@400.91,895
  Top Layer w15.6: R1.1@374.02,1043.31 374.02,1016.7 ccw(c414.34,1016.7) 385.83,988.19 ; 387.04,986.98 cw(c353.77,953.71) 400.82,953.71 C1.2@400.83,895
50R_SMA: C13.1 L2.1 P1.1 TP1.1 | length 765.8
  Top Layer w12: C13.1@530.65,1195 530.65,1160.16 L2.1@531,1159.81
  Top Layer w18: C13.1@532.94,1194.88 876.97,1194.88 ccw(c875.69,1257.97) 938.78,1256.69 ; 938.78,1259.25 cw(c875.69,1257.97) 938.78,1256.69 ; P1.1@1007.87,1519.68 1007.87,1415.04 cw(c907.87,1415.04) 978.58,1344.33 TP1.1@938.78,1304.53 938.78,1256.69
50R_UFL: P2.1 R2.2 | length 109.7
  Top Layer w15.6: P2.1@229.33,1041.34 P2.1@230.32,1042.32
  Top Layer w18: P2.1@230.32,1042.32 R2.2@338.58,1042.32
BOARD_ID_SCL: P200.39 TPJ14.1 U200.6 | length 449.3
  Bottom Layer w4: U200.6@933.07,746.06 933.07,735.28 943.05,725.3 967.42,725.3 TPJ14.1@1037.4,795.28 1064.96,822.83 1064.96,1084.05 P200.39@1065.55,1084.65
BOARD_ID_SDA: P200.40 TPJ15.1 U200.5 | length 520.8
  Bottom Layer w4: U200.5@952.76,746.06 952.76,755.91 962.13,765.28 988.7,765.28 1009.37,785.95 1009.37,815.47 1037.4,843.5 TPJ15.1@1037.4,897.64 1037.4,981.39 1047.34,991.33 1047.34,1026.01 1040.35,1032.99 1040.35,1144.69 1065.55,1169.88 P200.40@1065.55,1198.82
BOARD_ID_WP: R200.1 TPJ16.1 U200.7 | length 446.3
  Bottom Layer w4: U200.7@913.39,746.06 913.39,727.61 916,725 916,711 956,671 956,543.6 922.73,510.33 922.73,379.42 954.72,347.43 TPJ16.1@954.72,344.49
GND: AT1.2 C1.1 C5.2 C6.2 C10.2 C11.2 C12.2 C13.2 C14.2 C102.2 C103.2 C106.2 C107.2 C110.2 C111.2 C112.2 C113.2 C114.2 C115.2 C116.2 C117.2 C124.2 C200.2 C201.2 C203.2 C205.2 C207.2 P1.2 P1.3 P1.4 P1.5 P2.2 P2.3 P200.2 P200.38 P201.1 P201.39 SH100.1 TP1.2 TPJ13.1 U1.17 U1.18 U1.19 U1.37 U1.49@446.85,669.29 U100.B2 U200.2 U200.3 U200.4 X1.2 X1.4 | length 6985.9
  Top Layer w5: v1(176.18,597.44) 182.09,591.54 182.09,514.76 191.54,505.31 282.79,505.31 v1@314.88,537.4 ; v1(387.72,736.22) v1(387.72,702.75) 387.72,698.82 v1(387.72,669.29) v1(417.24,669.29) ; v1(417.24,702.75) v1(417.24,669.29) ; v1(446.77,702.75) v1(446.77,669.29) ; v1(446.77,736.22) 468.43,736.22 U1.49@476.3,728.35 ; v1(476.3,736.22) 497.95,736.22 U1.49@505.83,728.35 ; v1(505.83,669.29) v1(476.3,669.29) U1.49@446.85,669.29 v1(446.77,669.29) ; v1(505.83,702.75) U1.49@505.83,728.35 ; v1(505.83,736.22) U1.49@505.83,728.35 ; v1(417.24,669.29) v1(446.77,669.29)
  Top Layer w8: v1@351,908 351,897 353,895 C1.1@379.17,895 ; v1(353,886) 355.3,883.7 356.3,883.7 366.97,873.03 C107.2@372.05,873.03 ; v1@353,891.49 v1(353,907) ; v1@429,968 v1@431.1,968 ; C124.2@558.98,387.8 576.69,405.51 576.69,407.5 578.93,409.74 578.93,424.65 576.69,426.88 U100.B2@576.69,438.98 ; C14.2@578.83,877 580.91,879.09 580.91,893.91 v1(583,896) ; X1.4@622.88,798 625.65,800.77 C6.2@625.65,830 ; C103.2@626.98,655.48 627.7,656.19 650.63,656.19 ; C103.2@626.98,664.28 627.48,663.78 664.78,663.78 C102.2@665,664 665,662.03 659.16,656.19 650.63,656.19 ; v1(636.83,645.64) 640.07,645.64 650.63,656.19 ; C1.1@379.17,895 378.58,895 379.17,894.41 C1.1@379.17,895
  Top Layer w10: v1@314.88,537.4 U1.37@338.5,537.4 ; SH100.1@360.83,247.83 384.1,247.83 392.24,239.69 v1(392.24,203.1) ; v1@431,876.84 431,837 436,832 v1(447,832) v1@448.06,830.94 ; U1.49@437.01,679.13 U1.19@437.01,801.18 437.01,826.76 v1@439.12,828.88 ; 441,918.29 457,934.29 v1(457,937) ; v1(446.77,669.29) U1.49@505.83,728.35 ; v1(452.38,421.42) 454.25,423.29 454.25,442.44 C117.2@454.72,442.91 ; U1.49@456.61,761.73 U1.18@456.61,801.18 ; U1.18@456.69,801.18 456.69,810.87 448.91,818.65 448.91,830.09 v1@448.06,830.94 ; U1.49@476.3,761.73 U1.17@476.38,801.18 ; U1.17@476.38,801.18 476.38,810.87 456.3,830.94 v1@448.06,830.94 ; C110.2@480.24,387.8 481.81,386.22 480.32,384.72 v1(480.32,358.27) ; v1(583.29,196.01) 589.09,201.81 589.09,239.88 SH100.1@597.05,247.83 ; v1(821.38,196.38) 833.27,208.27 SH100.1@833.27,247.83
  Top Layer w12: v1(39.29,838.58) v1@39.29,840.55 ; C113.2@257.8,661.42 257.8,684.96 v1(257.87,685.04) ; v1(356.3,411.42) C115.2@383.74,411.42 ; C115.2@383.76,411.44 C115.2@387.72,407.48 ; v1(420.28,421.26) C116.2@420.28,442.91 ; v1@431.17,879.84 431.28,879.95 431.28,893 ; v1@432,873 431,874 v1(431,922.24) 431,967.9 431.1,968 428,971.1 428,988 407,1009 407,1023 404,1026 404,1074.8 435.04,1074.8 435.04,1123.03 v1@440.97,1128.96 ; v1(486.14,421.26) C114.2@486.14,444.88 ; 558.98,364.17 C124.2@558.98,387.8 ; C103.2@626.98,664.28 626.98,655.48 v1(636.83,645.64) ; X1.2@678,754.69 695.64,754.69 v1(708.66,767.72) ; SH100.1@1102.36,1218.5 v1(1102.36,1220.47) ; v1(366.06,444.88) 385.75,444.88 C111.2@387.72,442.91 368.03,442.91 v1(366.06,444.88)
  Top Layer w20: v1(279.54,834.69) 279.68,834.82 279.68,840.12 283.46,843.91 C106.2@283.46,866.14 283.46,882.81 ; 441,918.29 441,838 v1(447,832)
  Top Layer w25: v1(78.74,1348.42) 58.07,1348.43 ; v1@84.65,1100.39 P2.2@160.43,1100.39 ; SH100.1@90.55,982.28 P2.3@166.34,982.28 ; v1(159.45,1140.75) 159.45,1107.28 P2.2@166.34,1100.39 188.98,1100.39 213.58,1125 v1(213.58,1140.75) ; v1(164.37,952.76) 164.37,978.35 163.39,979.33 P2.3@166.34,982.28 ; v1(202.76,714.57) 202.76,704.72 C112.2@218.5,688.98 ; v1(224.41,982.28) P2.3@166.34,982.28 ; 58.07,1348.43 58.07,1382.41 AT1.2@51.11,1389.37 43.31,1381.57 v1(43.31,1348.43) 58.07,1348.43
  Top Layer w39.37: SH100.1@78.54,247.87 SH100.1@78.54,530.12 SH100.1@78.54,766.34 ; v1(78.56,649.61) v1(78.56,884.84) SH100.1@78.54,1002.56 ; SH100.1@78.98,1271.85 v1(78.56,1271.44) v1(159.45,1271.44) ; SH100.1@90.55,259.84 78.56,247.85 SH100.1@360.83,247.83 ; v1(322.83,1271.65) 323.03,1271.85 SH100.1@360.83,1271.85 SH100.1@411.22,1271.85 ; SH100.1@384.1,247.83 SH100.1@597.05,247.83 SH100.1@827.56,247.83 ; v1(411.42,1271.65) SH100.1@411.22,1271.85 ; v1(549.21,1271.65) SH100.1@549.41,1271.85 ; SH100.1@760.8,1271.65 597.24,1271.65 SH100.1@597.05,1271.85 SH100.1@549.41,1271.85 ; SH100.1@764.86,1271.65 833.07,1271.65 v1(833.27,1271.85) SH100.1@833.68,1271.44 ; SH100.1@833.27,247.83 SH100.1@1102.13,247.83 ; SH100.1@1015.75,1271.65 1015.96,1271.44 v1(1072.83,1271.44) SH100.1@1102.15,1271.44 ; SH100.1@1102.15,247.85 v1(1102.15,413.39) 1102.15,1002.15 SH100.1@1102.56,1002.56 ; SH100.1@411.22,1271.85 SH100.1@549.41,1271.85
  Signal Layer 3 w12: v1@590.58,1148.68 v1@591.51,1149.61
  Bottom Layer w10: C203.2@171.77,341.06 174.21,343.5 v1(192.91,343.5) ; C201.2@172.24,313.98 v1(192.91,313.98) 195.87,313.98 195.87,312.01 v1@195.39,311.54 ; C205.2@172.76,370.59 193.43,370.59 C205.2@194.41,371.58
  Bottom Layer w12: U200.2@913.39,860.24 913.39,879.92 v1(923.23,889.76) 933.07,879.92 U200.3@933.07,860.24 ; v1(940.99,499.04) 947.86,499.04 TPJ13.1@968.5,519.68 ; U200.4@952.76,860.24 992.13,860.24 994.09,860.24 1009.37,875.51 v1(1010.35,875.51) ; 984.06,1304.53 990.55,1311.02 v1(1012.8,1311.02)
  Bottom Layer w20: C207.2@646.65,723.43 702.76,723.43 v1@718.57,739.24
  Bottom Layer w25: P201.1@114.17,127.95 116.14,125.98 v1(88.58,125.98) v1(88.58,149.61) 105.71,149.61 P201.1@115.55,139.76 ; P200.2@115.55,1198.82 115.55,1296.65 v1(127.95,1309.06) ; C205.2@185.04,402.56 v1(218.5,402.56) ; v1(1015.75,1143.7) 1015.75,1198.62 P200.38@1015.55,1198.82 1015.55,1271.24 v1(1016.73,1272.42) ; P201.39@1065.55,139.76 1090.55,139.76 v1(1094.49,143.7) ; P201.39@1065.55,139.76 1069.49,143.7 v1(1094.49,143.7) ; P201.39@1065.55,139.76 1065.55,119.49 1068.9,116.14 1070.87,118.11 v1(1094.49,118.11) v1(1094.49,143.7)
  other v1: 76.69,41.34 190.87,41.34 228.27,41.34 265.67,41.34 303.07,41.34 338.5,41.34 373.94,41.34 407.4,41.34 440.87,41.34 476.3,41.34 511.73,41.34 547.17,41.34 580.63,41.34 616.06,41.34 649.53,41.34 682.99,41.34 716.46,41.34 749.92,41.34 785.35,41.34 818.82,41.34 854.25,41.34 889.69,41.34 925.12,41.34 960.55,41.34 994.02,41.34 1029.45,41.34 1066.85,41.34 1102.28,41.34 1139.69,41.34 39.29,43.31 1139.69,92.52 39.29,98.43 1139.69,141.73 39.29,149.61 687.99,193.9 914.37,196.85 990.16,197.83 1040.35,197.83 39.29,246.06 1139.69,251.97 1139.69,303.15 39.29,309.06 1053.15,324.8 1139.69,348.43 563.06,354.5 39.29,366.14 697.83,382.87 994.09,383.86 1053.15,383.86 1139.69,389.76 78.74,403.54 39.29,429.13 1139.69,429.13 944.88,433.07 994.09,433.07 1053.15,433.07 1139.69,474.41 39.29,482.28 994.09,482.28 1053.15,482.28 1139.69,517.72 1053.15,531.5 39.29,533.46 311.93,536.42 994.09,551.18 1139.69,561.02 39.29,584.65 1139.69,600.39 387.8,604.33 417.32,604.33 446.85,604.33 476.38,604.33 505.91,604.33 862,612 927.43,624 1053.15,629.92 39.29,635.83 387.72,635.83 417.24,635.83 446.77,635.83 476.3,635.83 505.83,635.83 889,640.37 1010.83,640.75 1139.69,643.7 1139.69,685.04 39.29,687.01 1053.15,688.98 476.3,702.75 1139.69,726.38 39.29,736.22 417.24,736.22 721,745 1013.78,748.03 1053.15,748.03 118.11,753.94 1139.69,769.68 39.29,789.37 118.11,801.18 1139.69,811.02 123.03,830.71 648.08,832.68 688,834.69 1139.69,854.33 431,879 39.29,887.8 119,890 160.43,889.76 974.41,895.67 1139.69,897.64 348,933 39.29,937.01 1139.69,942.91 277,944 117.13,946.85 577.84,950 366,951 974.41,954.72 1013.78,954.72 305,964 564.05,969 429.55,976.5 39.29,984.25 1139.69,986.22 811,988 261.81,992.13 299.21,992.13 338.58,992.13 319,1012 613,1011.81 403,1021 974.41,1023.62 761.85,1026.62 810.97,1026.62 861.22,1026.62 924.21,1026.62 39.29,1029.53 490,1029.1 571,1030 1139.69,1031.5 39.29,1082.68 1139.69,1084.65 84.61,1102.32 1094.49,1106.3 440.72,1134.31 674,1140.75 716,1141 761.22,1140.75 267.72,1141.73 358.27,1141.73 498,1142 866,1142 909.45,1141.73 972.44,1141.73 1064.96,1141.73 815,1142.74 639.87,1148 590.55,1149.61 1141.73,1196.85 39.37,1198.82 39.37,1236.22 1141.73,1236.22 39.37,1269.68 762.83,1273.68 1141.73,1273.62 39.37,1307.09 78.74,1309.05 179.13,1309.06 279.53,1309.05 322.83,1309.05 367.13,1309.05 411.42,1309.05 454.72,1309.05 501.97,1309.05 544.29,1309.06 588.58,1309.05 625,1309.05 667.32,1309.05 706.69,1309.05 750,1309.05 789.37,1309.05 827.76,1309.06 864.17,1310.04 1047.24,1311.02 1082.68,1311.02 1114.17,1311.02 1141.73,1311.02 842.52,1347.44 879.92,1347.44 111.22,1347.77 153.54,1347.77 257.87,1347.77 299.21,1347.77 343.5,1347.77 386.81,1347.77 432.09,1347.77 478.35,1347.77 519.69,1347.77 565.94,1347.77 606.3,1347.77 643.7,1347.77 684.06,1347.77 727.36,1347.77 766.73,1347.77 806.1,1347.77 1029.53,1348.43 1064.96,1348.43 1096.46,1348.43 1127.95,1348.43
NetC3_1: C3.1 C6.1 L6.1 L7.2 U1.13 | length 222.6
  Top Layer w8: C3.1@500,882.83 500,907 v2(501,908) ; U1.13@555,813 ccw(c555,821) U1.13@555.12,813 ; U1.13@555.12,801.18 U1.13@555.12,813 ; L7.2@604,854 C6.1@604,830 603.5,829.5 560.5,829.5 v1(560,829) 555.12,824.12 U1.13@555.12,813
  Signal Layer 3 w8: v2(501,908) v1(560,829)
NetC3_2: C3.2 L3.1 U1.15 | length 67.6
  Top Layer w6: C3.2@500,861.17 500.59,861.17 500.59,847.22 L3.1@514.81,833 L3.1@514,833 ; L3.1@515,833 515.4,832.6 515.4,801.53 U1.15@515.75,801.18
NetC4_1: C4.1 C8.2 L5.2 U1.14 | length 184.8
  Top Layer w8: C4.1@474,882.83 474,897 v2(478,897) ; C8.2@531.91,877.26 531.91,849 536,844.91 v1(536,830) 535.43,829.43 U1.14@535.43,801.18
  Signal Layer 3 w8: v2(478,897) v1(536,830)
NetC4_2: C4.2 L3.2 U1.16 | length 70.3
  Top Layer w6: C4.2@474,861.17 474.5,861.17 474.5,849.69 L3.2@491.19,833 L3.2@491,833 ; L3.2@492,834 492,832.19 496.06,828.13 U1.16@496.06,801.18
NetC8_1: C8.1 C10.1 L7.1 L8.2 | length 183.9
  Top Layer w8: C10.1@531,944.83 531,920 531,899.83 C8.1@532,898.83 ; 531.91,920 591.46,920 604,907.46 L7.1@604,877.62
  Top Layer w12: C10.1@531,944.83 L8.2@531,975.19
NetC11_1: C11.1 L8.1 L9.2 | length 57.4
  Top Layer w12: L8.1@531,996.81 L8.1@531,998.81 531,1025 L9.2@531,1054.19
NetC12_1: C12.1 L2.2 L9.1 | length 58.6
  Top Layer w12: C12.1@530.83,1107 530.83,1136.02 L2.2@531,1136.19 ; C12.1@530.91,1106.09 L9.1@531,1077.81 L9.1@531,1076.81
NetC14_1: C14.1 L4.2 L5.1 L6.2 | length 210
  Top Layer w8: v3(557,897) 557.09,896.91 C14.1@557.09,877.09 ; C14.1@557.17,877 557.17,848.64 L5.1@558.17,849.64 ; L5.1@559.35,850.81 L6.2@579,850.81
  Top Layer w12: L4.2@466,986 L4.2@466,984.66 468,982.66 468,975.25 475,968.25 v3(475,965)
  Signal Layer 3 w12: v3(475,965) 498.8,965 557,906.8 v3(557,897)
NetC102_1: C102.1 C103.1 L102.2 U1.9 | length 137.1
  Top Layer w10: U1.9@578.74,718.5 588.43,718.5 594.19,712.74 594.35,712.74 602.5,704.59 602.5,704.43 607.93,699 C103.1@632,699 632.22,699.22 664.78,699.22 C102.1@665,699.43 666.84,701.28 704.16,701.28 L102.2@706,703.12
NetC112_1: C112.1 C113.1 R100.2 U1.34 | length 143.7
  Top Layer w10: C113.1@257.8,625.98 264.39,619.39 264.39,608.27 275.52,597.14 291.26,597.14 294.51,600.39 U1.34@314.96,600.39
  Top Layer w12: 190.94,625.98 C113.1@257.8,625.98
NetC117_1: C117.1 U1.41 | length 71.8
  Top Layer w10: U1.41@417.24,537.4 417.24,515.75 C117.1@452.68,480.31
NetL1_1: L1.1 U1.20 | length 58.6
  Top Layer w8: L1.1@401,853 401,839 417.32,822.68 U1.20@417.32,801.18
NetL100_1: L100.1 U1.38 | length 106.8
  Top Layer w10: L100.1@292.85,472.11 317.58,472.11 358.19,512.72 U1.38@358.27,537.4
NetL101_2: L101.2 R100.1 | length 50.2
  Top Layer w12: L101.2@139.76,687.6 155.81,671.56 169,671.56 R100.1@179.13,661.42
NetU1_10: U1.10 X1.3 | length 149.5
  Top Layer w5: U1.10@578.74,738.19 595.81,738.19 605,729 640,729 650.59,739.59 650.59,769.59 677.17,796.17 X1.3@677.17,798
NetU1_11: U1.11 X1.1 | length 51.5
  Top Layer w5: U1.11@578.66,757.87 U1.11@578.74,757.87 620,757.87 622.88,760.76 X1.1@622.88,754.69
PAVDD: L103.1 R210.1 R211.1 | length 506.8
  Top Layer w25: v1(244.09,862.2) v1(244.09,883.86) 244.09,903.54 L103.1@250,909.45
  Signal Layer 3 w25: v1(163.39,533.46) v1(163.39,557.09) 165.43,557.09 169.37,553.15 221.46,605.24 221.46,686.1 260.82,725.46 260.82,773.7 244.09,790.43 v1(244.09,862.2) v1(244.09,883.86)
  Bottom Layer w25: v1(163.39,557.09) v1(163.39,533.46) 163.39,520.67 R210.1@173.23,510.83
RADIO_PA0: P200.19 P201.12 TPJ5.1 U1.25 | length 1549.9
  Top Layer w5: v1@295.28,787.4 305.12,777.56 U1.25@314.96,777.56
  Signal Layer 3 w4: v1(287.4,791.34) 287.4,792.31 308.33,813.24 321.85,813.24 324.21,815.61 337.71,815.61 412,889.89 412,981.58 422.92,992.5 578.19,992.5 646.65,924.04 v1(646.65,913.4)
  Bottom Layer w4: v1(287.4,791.34) 271.32,775.26 271.32,757.21 315.94,712.59 315.94,602.37 286.54,572.97 286.54,357.55 306.91,337.18 307.01,337.18 359.25,284.94 P201.12@359.25,283.46 ; P201.12@365.55,253.94 P201.12@365.55,279.13 ; P200.19@565.55,1084.65 565.55,1058.46 589.02,1035 615.63,1035 659,991.63 659,926 646.65,913.65 v1(646.65,913.4) 623.53,890.27 623.53,856.68 632,848.21 632,795.39 TPJ5.1@612.2,775.59
RADIO_PA1: P200.20 P201.14 TPJ6.1 U1.26 | length 2139.5
  Top Layer w5: v1(287.32,765.75) 295.2,757.87 U1.26@314.96,757.87
  Signal Layer 3 w4: v1(287.32,765.75) 334.19,765.75 342.61,757.33 617.93,757.33 676.63,698.63 738.03,698.63 747.68,688.98 v1(763.78,688.98) ; v1(749.53,898.15) 791.51,898.15 847,953.64 847,981.59 854.33,988.92 v1(854.33,993.11)
  Bottom Layer w4: v1(287.32,765.75) 324.8,728.27 324.8,599.92 294.54,569.66 294.54,360.86 310.23,345.18 310.32,345.18 352.35,303.15 394.69,303.15 P201.14@409.45,288.39 ; P200.20@565.55,1170.71 P200.20@565.55,1198.82 565.55,1226.97 605.32,1266.73 741.14,1266.73 753.71,1254.16 797.02,1254.16 802.17,1249.02 833.66,1249.02 844.98,1237.69 844.98,1001.47 v1@854.33,992.13 ; TPJ6.1@748.82,868.9 748.82,866.37 800.68,814.51 800.68,728.32 763.78,691.42 v1(763.78,688.98) ; TPJ6.1@749.53,868.9 v1(749.53,898.15)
